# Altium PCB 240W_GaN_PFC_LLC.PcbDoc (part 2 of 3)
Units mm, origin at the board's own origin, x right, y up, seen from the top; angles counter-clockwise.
Board outline 120 x 71.8 mm, 4 copper layers (Top Layer, Layer 1, Layer 2, Bottom Layer), stack 1.787 mm thick; 163 components, 87 nets, 528 pads, 288 vias.
Unrouted connection lines stored in the file: 3.
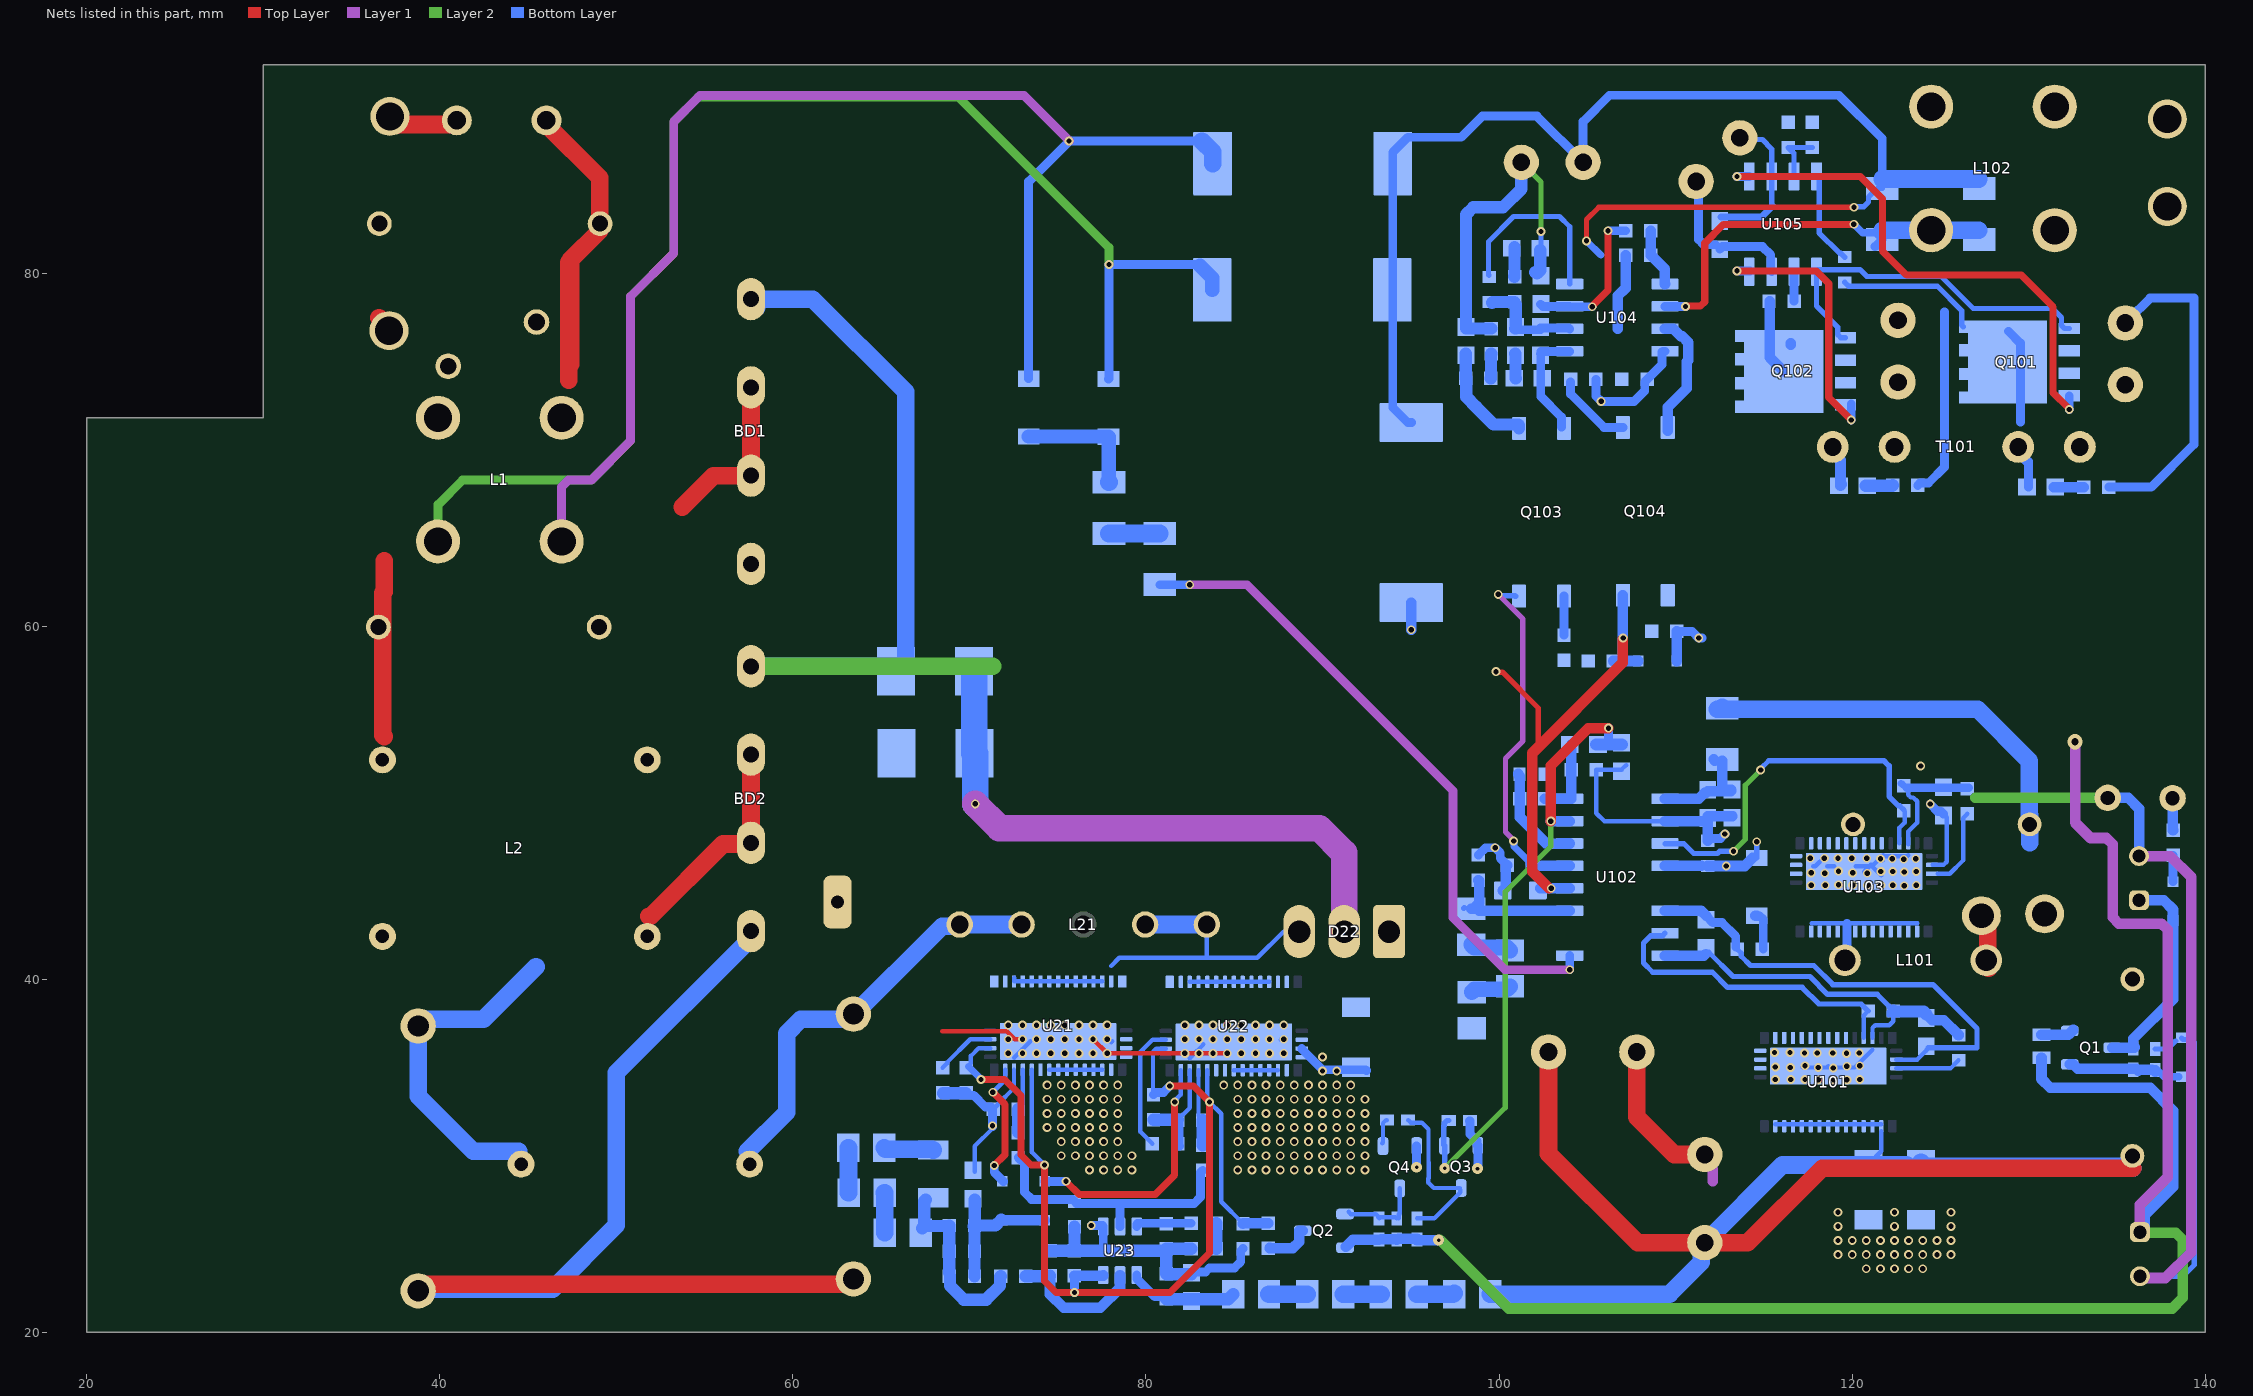
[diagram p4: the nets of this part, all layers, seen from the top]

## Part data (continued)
R121: library part CMP-0023052-4, "RES, 360 k, 1%, 0.1 W, 0603", Manufacturer=Yageo, Power_W=100mW, Supplier Part Number 1=311-360KHRCT-ND, TempCo="100 ppm/C", Tolerance_%=1%, Value2=0.1W, Value_Code=360k
R123: library part CMP-0025821-4, "RES, 4.7, 5%, 0.1 W, AEC-Q200 Grade 0, 0603", Manufacturer=Vishay-Dale, Power_W=100mW, Supplier Part Number 1=541-4.7GCT-ND, TempCo="200 ppm/C", Tolerance_%=5%, Value2=0.1W, Value_Code=4R70, ValueDisplayed=4.7
R124: library part CMP-0023201-5, "RES, 5.49 k, 1%, 0.1 W, 0603", Manufacturer=Yageo, Power_W=100mW, Supplier Part Number 1=311-5.49KHRCT-ND, TempCo="100 ppm/C", Tolerance_%=1%, Value2=0.1W, Value_Code=5k49, ValueDisplayed=5.49k
R125: library part CMP-0022919-4, "RES, 221 k, 1%, 0.1 W, 0603", Manufacturer=Yageo, Power_W=100mW, Supplier Part Number 1=311-221KHRCT-ND, TempCo="100 ppm/C", Tolerance_%=1%, Value2=0.1W, Value_Code=221k
R126: library part CMP-0025768-4, "RES, 2.0 k, 5%, 0.1 W, AEC-Q200 Grade 0, 0603", Manufacturer=Vishay-Dale, Power_W=100mW, Supplier Part Number 1=541-2.0KGCT-ND, TempCo="200 ppm/C", Tolerance_%=5%, Value2=0.1W, Value_Code=2k00, ValueDisplayed=2.0k
R127: library part CMP-0022879-5, "RES, 1.47 k, 1%, 0.1 W, 0603", Manufacturer=Yageo, Power_W=100mW, Supplier Part Number 1=311-1.47KHRCT-ND, TempCo="100 ppm/C", Tolerance_%=1%, Value2=0.1W, Value_Code=1k47, ValueDisplayed=1.47k
R128 R129: library part CMP-0025712-4, "RES, 12, 5%, 0.1 W, AEC-Q200 Grade 0, 0603", Manufacturer=Vishay-Dale, Power_W=100mW, Supplier Part Number 1=541-12GCT-ND, TempCo="200 ppm/C", Tolerance_%=5%, Value2=0.1W, Value_Code=12R0, ValueDisplayed=12
R130 R131: library part CMP-0025912-5, "RES, 330, 5%, 0.1 W, 0603", Manufacturer=Yageo, Power_W=100mW, Supplier Part Number 1=311-330GRCT-ND, TempCo="100 ppm/C", Tolerance_%=5%, Value2=0.1W, Value_Code=330R, ValueDisplayed=330
R132: library part CMP-0022822-4, "RES, 162 k, 1%, 0.1 W, 0603", Manufacturer=Yageo, Power_W=100mW, Supplier Part Number 1=311-162KHRCT-ND, TempCo="100 ppm/C", Tolerance_%=1%, Value2=0.1W, Value_Code=162k
RV1: library part CMP-0001908-4, "VARISTOR 450V 1.2KA DISC 7MM", Manufacturer=Littelfuse
T101: library part XFRM_LLC
TP1 TP2 TP101 TP102 TP103 TP104 TP105 TP106: library part CMP-0055148-1, "Test Point, Multipurpose, Black, TH", Color=Black, Manufacturer=Keystone, PartNumber=5011, Supplier Part Number 1=36-5011-ND
U21 U22: library part CMP-0096535-2, "650-V GaN FET With Integrated Driver and Current Sense Emulation", Manufacturer="Texas Instruments", Max Supply Voltage=26V, Min Supply Voltage=10V, Operating Temperature Range="-40°C to +175°C"
U23: library part CMP-0860501-1, "6-Pin Single-Phase Transition-Mode PFC Controller, DBV0006A (SOT-23-6)", Alternate Manufacturer="Texas Instruments", Operating Temperature Range="-40 to 125 C", Rating=Catalog
U101 U103: library part CMP-0121224-1, "Power Switch/Driver 1:1 N-Channel 7.7A 38-VQFN (8x5.3)", Digikey Part Number=296-LMG3612REQRCT-ND, Manufacturer="Texas Instruments", Max Supply Voltage=26V, Min Supply Voltage=10V, Mouser Part Number=595-LMG3612REQR, Nominal Supply Current=2.2mA, Operating Temperature Range="-40°C to +125°C", Part Number=LMG3612REQR
U102: library part CMP-0095300-2, "750kHz Wide VIN/VOUT Range LLC Controller Optimized for Light Load Efficiency", Manufacturer="Texas Instruments", Max Supply Voltage=18.5V, Operating Temperature Range="-40°C to +150°C", Switching Frequency=30-750kHz
U104: library part CMP-0121574-1, "Dual, 36-V 1.2-MHz low-offset-voltage operational amplifier with internal reference 8-SOIC -40 to 125", Digikey Part Number=296-TL103WBIDRCT-ND, Input Bias Current=-0.015uA, Input Offset Voltage=0.3mV, Manufacturer="Texas Instruments", Max Supply Voltage=36V, Min Supply Voltage=3V, Mouser Part Number=595-TL103WBIDR, Nominal Supply Current=0.55mA, Operating Temperature Range="-40°C to +125°C", Output Current Per Channel=24mA, Voltage Gain=210V/mV
U105: library part CMP-0121571-1, "Power Supply Controller Flyback, Forward Converters, LLC 8-SOIC", Digikey Part Number=1589-MP6924AGS-PTR-ND, Manufacturer="Monolithic Power Systems", Max Power Dissipation=1.4W, Max Supply Voltage=35V, Min Supply Voltage=4.2V, Mouser Part Number=946-MP6924AGS-P, Nominal Supply Current=4.6-16mA, Operating Temperature Range="-40°C to +125°C"

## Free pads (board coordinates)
  rrect50% 1.6x3 hole 0.762 slot 2 at 90 deg: 13(62.525,44.375)

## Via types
v1: diameter 0.5, hole 0.3, Top Layer to Bottom Layer, tented both sides, 283 vias
v2: diameter 0.61, hole 0.203, Top Layer to Bottom Layer, tented both sides, 4 vias
v3: diameter 0.864, hole 0.406, Top Layer to Bottom Layer, tented both sides, 1 vias

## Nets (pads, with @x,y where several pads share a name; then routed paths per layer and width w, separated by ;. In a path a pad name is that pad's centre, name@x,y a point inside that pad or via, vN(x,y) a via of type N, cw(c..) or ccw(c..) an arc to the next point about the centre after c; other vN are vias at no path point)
5VP: C114.1 R119.2 R120.2 U102.8 | length 4.5
  Bottom Layer w0.6: R120.2@102.597,50.229 U102.8@104,50.229 104.089,50.229 C114.1@104.089,51.874 R119.2@104.089,53.272
390V_BUS: C29.1 C30.1 C31.1 C103.1 C122.1 C123.1 D21.1 D22.2 D25.1 R21.2 R109.1 U101.2 U101.3 U101.4 U101.5 U101.6 U101.7 U101.8 U101.9 U101.10 U101.11 U101.12 U101.13 U101.14 | length 125.2
  Top Layer w1: C29.1@102.8,35.875 102.8,30.124 107.849,25.075 C30.1@111.65,25.075 114.071,25.075 118.296,29.3 135.875,29.3
  Layer 1 w1.5: v1(70.325,49.935) 71.696,48.564 89.814,48.564 91.225,47.153 D22.2@91.225,42.7
  Bottom Layer w0.25: U101.14@115.65,31.775 U101.9@118.15,31.775 ; U101.8@118.65,31.775 U101.9@118.15,31.775 ; U101.5@120.15,31.775 U101.4@120.65,31.775 ; C122.1@120.925,29.625 121.025,29.625 121.65,30.25 U101.2@121.65,31.4 ; U101.2@121.65,31.775 U101.4@120.65,31.775 ; U101.9@118.15,31.775 U101.4@120.65,31.775
  Bottom Layer w1: R21.2@99.491,22.15 109.649,22.15 111.459,23.96 111.459,24.884 C30.1@111.65,25.075 116.05,29.475 119.85,29.475 119.862,29.488 122.837,29.488 122.85,29.5 123.075,29.5 ; C29.1@103.15,35.925 C29.1@103.2,35.875 ; C123.1@123.9,29.625 124.125,29.4 135.775,29.4 135.875,29.3
  Bottom Layer w1.5: D25.1@70.26,57.45 70.273,57.437 70.273,52.812 D21.1@70.285,52.8 70.325,52.76 v1(70.325,49.935)
BD+: BD1.1 BD2.1 C25.1 D21.2 D25.2 L22.1 | length 68.9
  Layer 2 w1: BD2.1@57.625,57.725 71.315,57.725
  Bottom Layer w1: L22.1@44.475,30.25 41.9,30.25 38.775,33.375 38.775,37.725 42.475,37.725 45.45,40.7 ; BD2.1@57.625,57.725 66.382,57.725 66.382,73.268 61.123,78.527 57.948,78.527 57.948,78.05 57.625,78.373 BD1.1@57.625,78.527
FB: C116.1 Q103.6 U102.5 | length 20.1
  Layer 1 w0.3: v1(99.95,61.8) 101.347,60.403 101.347,53.496 100.358,52.507 100.358,48.346 100.825,47.879 v1(100.825,47.825) v1@100.871,47.825
  Bottom Layer w0.3: v1(99.95,61.8) 100.004,61.8 100.079,61.725 100.888,61.725 100.913,61.7 Q103.6@100.95,61.7
  Bottom Layer w0.4: v1(100.825,47.825) 100.844,47.806 100.844,47.509 C116.1@101.805,46.548
  Bottom Layer w0.6: C116.1@101.805,46.548 C116.1@101.886,46.467 ; C116.1@101.955,46.419 U102.5@104,46.419
HB: C101.1 C121.2 R106.2 U101.36 U102.14 | length 26.7
  Bottom Layer w0.25: U101.36@122.5,35.45 123.691,35.45 C101.1@124.2,35.959 ; C101.1@124.2,35.984 C101.1@124.316,36.1
  Bottom Layer w0.3: R106.2@113.489,41.7 113.72,41.469 113.72,41.299 114.245,40.774 117.824,40.774 118.905,39.693 124.583,39.693 127.065,37.21 127.065,36.125 127.075,36.125 ; C101.1@124.301,36.125 127.05,36.125
  Bottom Layer w0.5: C121.2@111.725,43.591 112.11,43.206 112.63,43.206 113.408,42.428 R106.2@113.408,41.831
  Bottom Layer w0.6: U102.14@109.4,43.879 111.437,43.879 C121.2@111.725,43.591
HO: C102.1 U101.31 U102.15 | length 18.1
  Bottom Layer w0.25: U101.31@120.65,36.675 120.65,37.947 C102.1@120.903,38.2
  Bottom Layer w0.3: U102.15@109.4,42.609 109.25,42.459 108.58,42.459 108.175,42.054 108.175,40.926 108.707,40.394 110.375,40.394 112.085,40.394 112.94,39.539 117.166,39.539 118.112,38.593 120.51,38.593 C102.1@120.903,38.2
HV: R2.1 U102.1 | length 37.3
  Layer 1 w0.5: v1(82.475,62.348) 85.722,62.348 97.392,50.678 97.392,43.48 100.334,40.537 v1(104,40.537)
  Bottom Layer w0.5: R2.1@80.775,62.35 80.777,62.348 v1(82.475,62.348) ; v1(104,40.537) U102.1@104,41.339
ISNS: C108.2 C120.1 R113.2 U102.9 | length 6.2
  Bottom Layer w0.6: U102.9@109.4,50.229 111.314,50.229 111.652,50.566 111.744,50.566 111.825,50.647 113.119,50.647 113.14,50.669 113.14,50.721 112.65,50.721 C108.2@112.65,52.375 ; C108.2@112.15,52.45 C108.2@112.225,52.375
LL: R120.1 R132.2 U102.6 | length 6
  Bottom Layer w0.6: R132.2@101.075,51.65 101.075,51.598 101.175,51.498 R120.1@101.175,50.229 ; R120.1@101.182,50.229 101.182,49.186 102.688,47.68 103.371,47.68 103.379,47.689 U102.6@104,47.689
LMG_VCC: C21.2 C23.2 C36.1 C39.1 R32.1 U21.30 U21.36 U22.30 U22.36 U23.3 | length 65.8
  Top Layer w0.4: v1(70.65,34.325) 71.994,34.325 72.911,33.408 72.911,30.053 73.489,29.475 v1(74.255,29.475) 74.255,22.905 74.91,22.25 v1(75.95,22.25) 81.35,22.25 ; 77.868,22.25 81.35,22.25 ; v1(81.35,33.95) 82.7,33.95 v1(83.6,33.05) 83.6,24.5 81.35,22.25
  Bottom Layer w0.25: C21.2@69.975,35.136 70.081,35.242 70.081,35.656 70.525,36.1 U21.36@71.175,36.1 ; U21.30@73.525,34.875 73.525,30.211 v1@74.265,29.471 ; C23.2@80.425,33.461 80.397,33.489 80.397,35.891 80.579,36.073 U22.36@81.125,36.073 ; v1@83.475,33.155 U22.30@83.475,34.848 ; v1@83.6,33.028 84.255,32.373 84.255,27.401 C36.1@85.495,26.161
  Bottom Layer w0.254: v1@81.283,33.95 v1(81.35,33.95)
  Bottom Layer w0.4: C21.2@69.946,35.056 70.65,34.352 v1(70.65,34.325)
  Bottom Layer w0.5: v1(75.95,22.25) C39.1@75.95,23.2 ; C23.2@80.425,33.461 80.556,33.592 80.992,33.592 v1(81.35,33.95)
  Bottom Layer w0.6: C39.1@75.95,23.2 C39.1@75.948,23.202 77.577,23.202 U23.3@77.577,23.243 ; C36.1@85.495,26.161 85.502,26.168 86.928,26.168 R32.1@86.935,26.175
LO: C111.1 U102.11 U103.31 | length 21.7
  Layer 2 w0.3: v1(113.275,47.25) 113.943,47.918 113.943,50.983 114.8,51.84 v1@114.8,51.875
  Bottom Layer w0.25: U103.31@122.675,47.7 122.675,48.575 122.975,48.875 122.975,49.525 C111.1@122.95,49.55
  Bottom Layer w0.3: U102.11@109.416,47.674 110.476,47.674 111.025,47.125 112.371,47.125 112.495,47.25 v1(113.275,47.25) ; v1@114.85,51.955 115.274,52.379 121.801,52.379 ; 121.84,52.34 122.095,52.085 122.095,50.357 122.632,49.82 122.694,49.82 C111.1@122.925,49.589
  other v1: 114.816,51.856
NetBD1_2: BD1.2 BD1.3 L2.3 | length 9.6
  Top Layer w1: 53.725,66.75 55.502,68.527 BD1.3@57.625,68.527 BD1.2@57.625,73.527
NetBD2_2: BD2.2 BD2.3 L2.4 | length 12.5
  Top Layer w1: 51.85,43.575 51.952,43.575 56.037,47.66 57.56,47.66 BD2.3@57.625,47.725 BD2.2@57.625,52.725
NetC1_1: C1.1 L1.1 RV1.2 TP1.1 | length 1.1
  Top Layer w1: TP1.1@36.55,77.477 37.125,76.902 TP1.1@37.125,76.575
NetC1_2: C1.2 F1.1 L1.2 RV1.1 | length 28
  Top Layer w1: F1.1@46.015,88.425 49.05,85.39 49.05,82.95 49.05,82.4 47.4,80.75 47.4,74.837 ; 47.3,73.925 47.3,74.837 ; 47.3,74.837 47.3,80.6 47.3,74.837
NetC2_1: C2.1 CY1.1 D3.2 L1.4 L2.2 | length 88.6
  Top Layer w1: C2.1@36.775,59.95 36.775,61.875 ; 36.85,53.75 36.775,53.825 36.775,61.875 ; 36.852,63.702 36.852,61.952 36.775,61.875
  Layer 2 w0.5: L1.4@39.9,64.8 39.9,66.887 41.283,68.27 48.57,68.27 50.8,70.5 50.8,78.675 53.25,81.125 53.25,88.575 54.65,89.975 69.368,89.975 77.903,81.44 77.903,80.488 v1(77.9,80.484)
  Bottom Layer w0.5: D3.2@77.875,74 77.9,74.025 v1(77.9,80.484) 82.979,80.484 CY1.1@83.05,80.413
  Bottom Layer w0.8: CY1.1@83.05,80.413 83.75,79.713 CY1.1@83.75,79.05
NetC2_2: C2.2 CY2.1 D2.2 L1.3 L2.1 | length 74.7
  Layer 1 w0.5: L1.3@46.9,64.8 46.9,67.9 47.275,68.275 48.575,68.275 50.8,70.5 50.8,78.675 53.25,81.125 53.25,88.575 54.725,90.05 73.096,90.05 v1@75.671,87.475
  Bottom Layer w0.5: D2.2@73.35,74.013 73.35,85.182 v1(75.643,87.475) CY2.1@83.175,87.475
  Bottom Layer w1: CY2.1@83.175,87.475 83.775,86.875 CY2.1@83.775,86.2
NetC3_2: C3.2 Q2.1 Q4.3 R6.1 | length 4.7
  Bottom Layer w0.254: Q2.1@91.475,26.825 91.6,26.7 93.027,26.7 93.2,26.527 C3.2@93.2,26.525 ; C3.2@93.15,26.525 C3.2@93.2,26.525 ; C3.2@93.2,26.45 C3.2@93.2,26.525 ; R6.1@94.2,26.45 94.125,26.525 C3.2@93.2,26.525 ; R6.1@94.325,26.45 94.325,26.675 94.375,26.725 Q4.3@94.375,28.15
NetC9_1: C9.1 D4.1 Q1.1 R4.1 | length 6.4
  Bottom Layer w0.4: C9.1@137.2,34.95 137.675,34.475 D4.1@138.5,34.475
  Bottom Layer w0.6: Q1.1@132.325,35.175 132.525,35.175 132.775,34.925 135.925,34.925 136.1,34.925 R4.1@136.2,34.825 ; R4.1@136.2,34.875 C9.1@136.975,34.875 ; C9.1@137.175,34.75 C9.1@137.175,34.85
NetC22_1: C22.1 R34.2 U21.31 | length 3.3
  Bottom Layer w0.25: C22.1@73.025,32.89 U21.31@73.025,34.875
  Bottom Layer w0.7: R34.2@72.77,31.317 C22.1@72.77,32.635
NetC24_1: C24.1 R38.1 U22.31 | length 4.3
  Bottom Layer w0.25: U22.31@82.975,34.848 82.975,32.261 C24.1@83.211,32.025
  Bottom Layer w0.7: R38.1@83.211,30.606 C24.1@83.211,32.025
NetC27_1: C27.1 L21.1 L21.2 L22.2 | length 23.5
  Bottom Layer w1: L22.2@57.425,30.25 59.65,32.475 59.65,36.925 60.45,37.725 63.175,37.725 68.454,43.004 69.354,43.004 L21.1@69.45,43.1 L21.2@72.95,43.1
NetC28_1: C28.1 D22.1 D22.3 L21.4 L21.5 R22.2 U21.1 U21.2 U21.3 U21.4 U21.5 U21.6 U21.7 U21.8 U21.9 U21.10 U21.11 U21.12 U21.13 U21.14 U21.15 U22.1 U22.2 U22.3 U22.4 U22.5 U22.6 U22.7 U22.8 U22.9 U22.10 U22.11 U22.12 U22.13 U22.14 | length 29.3
  Bottom Layer w0.254: U21.3@72.525,40.096 U21.3@72.525,39.875 U21.4@73.025,39.875 U21.5@73.525,39.875 U21.6@74.025,39.875 U21.7@74.525,39.875 U21.8@75.025,39.875 U21.9@75.525,39.875 U21.10@76.025,39.875 U21.11@76.525,39.875 U21.12@77.025,39.875 U21.13@77.525,39.875 ; 78.025,40.75 78.484,41.209 83.436,41.209 ; U22.3@82.475,39.848 U22.4@82.975,39.848 U22.5@83.475,39.848 U22.6@83.975,39.848 U22.7@84.475,39.848 U22.8@84.975,39.848 U22.9@85.475,39.848 U22.10@85.975,39.848 U22.11@86.475,39.848 U22.12@86.975,39.848 ; L21.5@83.45,43.1 83.45,41.224 83.436,41.209 ; D22.3@87.789,42.694 86.304,41.209 83.436,41.209
  Bottom Layer w1: R22.2@65.166,30.45 65.241,30.375 67.9,30.375 C28.1@67.95,30.325 ; L21.4@79.95,43.1 L21.5@83.45,43.1 ; D22.3@88.685,41.884 D22.3@88.685,42.7
NetC28_2: C28.2 C32.1 C33.1 R27.1 R29.2 R33.2 | length 10.4
  Bottom Layer w0.7: R27.1@67.325,25.9 R27.1@67.433,26.008 ; C28.2@67.525,27.5 67.508,27.5 67.433,27.425 R27.1@67.433,26.008 ; C32.1@68.864,23.375 R29.2@68.864,24.6 C33.1@68.864,26.05 68.833,26.019 67.444,26.019 R27.1@67.433,26.008 ; C32.1@68.895,23.206 68.895,22.635 69.68,21.85 70.948,21.85 71.733,22.635 71.733,23.144 R33.2@71.764,23.175
NetC37_1: C37.1 C38.1 U23.6 | length 3.2
  Bottom Layer w0.5: U23.6@79.477,25.993 79.477,26.125 79.527,26.175 C37.1@82.564,26.175
NetC37_2: C37.2 R35.2 | length 1.4
  Bottom Layer w0.7: R35.2@83.986,24.725 C37.2@83.986,26.175
NetC40_1: C40.1 R33.1 U23.2 | length 7.9
  Bottom Layer w0.6: C40.1@74.564,23.195 74.564,22.164 75.336,21.393 77.409,21.393 78.527,22.51 U23.2@78.527,23.243
  Bottom Layer w0.7: R33.1@73.186,23.175 73.196,23.185 74.554,23.185 C40.1@74.564,23.195
NetC41_1: C41.1 R30.1 R37.2 U23.1 | length 6.3
  Bottom Layer w0.5: U23.1@79.477,23.243 79.477,23.043 80.504,22.017 C41.1@81.022,22.017 ; C41.1@81.019,22.02 C41.1@81.022,22.017 ; C41.1@81.094,22.017 C41.1@81.022,22.017 ; C41.1@81.15,21.889 C41.1@81.022,22.017
  Bottom Layer w0.7: C41.1@81.15,21.889 81.162,21.876 82.562,21.876 82.575,21.864 84.649,21.864 R30.1@84.934,22.15
NetC103_2: C103.2 C108.1 C109.1 TP103.1 | length 23.7
  Bottom Layer w1: C108.1@112.362,55.283 C108.1@112.762,55.283 ; C108.1@112.65,55.395 C108.1@112.762,55.283 ; C109.1@130.032,49.232 130.032,52.359 127.108,55.283 C108.1@112.762,55.283 ; 130.05,47.725 C109.1@130.05,49.3
NetC113_2: C113.2 R116.2 | length 1.4
  Bottom Layer w0.7: R116.2@99.536,74.045 99.543,74.052 99.543,75.427 C113.2@99.55,75.434
NetC118_1: C118.1 R103.1 R104.2 R118.2 U104.2 | length 5.8
  Bottom Layer w0.5: R118.2@100.925,76.856 100.991,76.79 C118.1@102.35,76.79 ; C118.1@102.35,76.89 103.95,76.89 U104.2@104,76.84
  Bottom Layer w0.7: R104.2@99.6,78.325 99.639,78.364 R103.1@100.875,78.364 ; R118.2@100.925,76.856 100.938,76.869 R103.1@100.938,78.221
NetC118_2: C118.2 C119.2 Q103.3 U104.1 | length 6.3
  Bottom Layer w0.5: C118.2@102.368,75.452 102.35,75.434 102.356,75.428 102.356,74.051 102.361,74.045 102.361,73.014 103.528,71.847 Q103.3@103.528,71.275 ; C118.2@102.368,75.552 103.982,75.552 U104.1@104,75.57
NetC119_1: C119.1 R118.1 | length 1.4
  Bottom Layer w0.7: R118.1@100.925,75.434 100.932,75.427 100.932,74.052 C119.1@100.939,74.045
NetC125_1: C125.1 R128.1 | length 1.7
  Bottom Layer w0.6: C125.1@131.411,67.875 R128.1@133.114,67.875
NetC126_1: C126.1 R129.1 | length 1.5
  Bottom Layer w0.7: C126.1@120.761,67.95 120.774,67.963 122.276,67.963 R129.1@122.289,67.975
NetC127_2: C127.2 R107.2 U105.3 | length 3.2
  Bottom Layer w0.3: U105.3@116.71,85.475 116.71,86.779 C127.2@116.375,87.114 R107.2@117.75,87.114
NetD1_2: D1.2 Q1.2 | length 1.9
  Bottom Layer w0.6: D1.2@130.725,36.85 132.25,36.85 Q1.2@132.525,37.125
NetD2_1: D2.1 D3.1 R1.2 | length 7.1
  Bottom Layer w0.8: D2.1@73.362,70.737 77.863,70.737 D3.1@77.875,70.725 ; R1.2@77.888,68.162 D3.1@77.888,70.712
  Bottom Layer w1: R1.2@77.888,68.162 R1.2@77.9,68.15
NetD23_2: D23.2 U21.33 | length 7.4
  Top Layer w0.4: v1(71.325,33.6) 72.009,32.916 72.009,30.059 v1(71.4,29.45)
  Bottom Layer w0.25: v1@71.325,33.606 72.025,34.306 U21.33@72.025,34.875
  Bottom Layer w0.5: v1(71.4,29.45) 71.4,29.075 D23.2@71.925,28.55
NetD24_2: D24.2 U22.33 | length 14.2
  Top Layer w0.4: v1(75.473,28.553) 76.218,27.808 80.522,27.808 81.625,28.91 v1(81.625,33.05)
  Bottom Layer w0.25: v1(81.625,33.05) 81.625,33.118 81.975,33.468 U22.33@81.975,34.848
  Bottom Layer w0.5: D24.2@74.275,28.55 75.471,28.55 v1(75.473,28.553)
NetD101_2: D101.2 R123.1 | length 1.5
  Bottom Layer w0.5: D101.2@138.175,45.525 R123.1@138.175,47.025
NetD102_1: D102.1 R106.1 | length 2.2
  Bottom Layer w0.5: D102.1@114.6,43.6 114.753,43.6 114.961,43.391 R106.1@114.961,41.7
  Bottom Layer w0.6: D102.1@114.525,43.6 D102.1@114.6,43.6
NetF1_2: F1.2 TP2.1 | length 3.8
  Top Layer w1: TP2.1@37.125,88.4 37.137,88.413 40.922,88.413 F1.2@40.935,88.425
NetL101_4: L101.4 TP102.1 | length 3
  Top Layer w1: TP102.1@127.65,43.55 127.687,43.512 127.687,40.663 L101.4@127.725,40.625
NetL102_1: L102.1 TP106.1
NetL102_2: L102.2 TP101.1
NetQ2_3: Q2.3 R32.2 | length 2.7
  Bottom Layer w0.6: R32.2@87,24.775 87,24.769 87.016,24.753 88.301,24.753 88.675,25.126 88.675,25.75 Q2.3@88.875,25.75
NetQ3_3: Q3.3 R5.1 R7.2 | length 9.5
  Bottom Layer w0.254: R7.2@94.85,32.025 95.006,31.869 95.631,31.869 96.002,31.498 96.002,29.637 96.007,29.632 96.007,28.732 96,28.725 96,28.475 96.3,28.175 Q3.3@97.775,28.175 ; R5.1@95.35,26.45 96.325,26.45 97.8,27.925 Q3.3@97.8,28.075
NetQ4_1: Q4.1 R7.1 | length 1.5
  Bottom Layer w0.254: Q4.1@93.375,30.7 93.425,30.75 93.425,31.852 93.598,32.025 R7.1@93.65,32.025
NetQ101_4: Q101.4 U105.1 | length 30.3
  Top Layer w0.4: v1(113.475,85.475) 120.457,85.475 121.707,84.225 121.707,81.255 123.066,79.896 129.577,79.896 131.388,78.086 131.388,73.215 v1@132.25,72.353 ; v1@132.25,72.352 v1@132.299,72.303
  Bottom Layer w0.5: v1(113.475,85.475) U105.1@114.17,85.475 ; v1(132.3,72.275) Q101.4@132.3,73.05
NetQ103_1: Q103.1 R116.1 R117.1 | length 6.4
  Bottom Layer w0.7: R117.1@98.125,75.434 98.119,75.428 98.119,74.051 R116.1@98.114,74.045 R116.1@98.145,74.014 ; R116.1@98.145,74.114 R116.1@98.145,74.014 ; Q103.1@101.125,71.2 101.125,71.388 101.088,71.425 99.688,71.425 98.703,72.41 98.703,72.42 98.145,72.978 R116.1@98.145,74.014
NetQ103_4: Q103.4 R112.2 | length 2.2
  Bottom Layer w0.5: R112.2@103.678,59.486 Q103.4@103.678,61.7
NetQ104_1: Q104.1 R126.2 | length 4.4
  Bottom Layer w0.5: R126.2@104.05,73.825 104.05,73.15 105.95,71.25 Q104.1@107.013,71.25
NetQ104_3: Q104.3 U104.7 | length 7.1
  Bottom Layer w0.6: U104.7@109.4,76.84 109.875,76.84 110.295,76.42 110.373,76.42 110.725,76.068 110.725,75.072 110.625,74.972 110.625,73.475 109.55,72.4 Q104.3@109.55,71.075
NetR1_1: R1.1 R2.2 | length 2.9
  Bottom Layer w1: R1.1@77.9,65.25 R2.2@80.775,65.25
NetR3_1: R3.1 R103.2 | length 1.7
  Bottom Layer w0.7: R103.2@100.85,79.811 R103.2@100.875,79.786 R3.1@100.875,81.475
NetR21_1: R21.1 R23.2 | length 2.2
  Bottom Layer w0.254: R23.2@95.338,22.222 R23.2@95.341,22.222
  Bottom Layer w1: R23.2@95.341,22.15 97.392,22.15 R21.1@97.464,22.222
NetR22_1: R22.1 R26.2 | length 2.6
  Bottom Layer w1: R22.1@63.134,30.45 63.146,30.437 63.146,27.913 R26.2@63.159,27.9
NetR23_1: R23.1 R28.2 | length 2.1
  Bottom Layer w1: R28.2@91.166,22.15 R23.1@93.309,22.15
NetR24_2: R24.2 U21.37 | length 3.4
  Bottom Layer w0.25: R24.2@68.475,34.986 68.731,35.242 68.731,35.287 70.044,36.6 U21.37@71.175,36.6
NetR25_2: R25.2 U22.37 | length 7.2
  Bottom Layer w0.25: R25.2@80.364,30.675 79.669,31.37 79.669,35.87 80.015,36.216 80.372,36.573 U22.37@81.125,36.573
NetR26_1: R26.1 R27.2 | length 2.3
  Bottom Layer w1: R26.1@65.191,27.9 65.2,27.891 65.2,25.656 R27.2@65.209,25.647
NetR28_1: R28.1 R30.2 | length 2.2
  Bottom Layer w1: R30.2@86.966,22.15 R28.1@89.134,22.15
NetR101_2: R101.2 U101.37 | length 4
  Bottom Layer w0.25: U101.37@122.5,34.95 125.57,34.95 126.025,35.405 R101.2@126.025,35.414 ; R101.2@125.792,35.174 R101.2@126.022,35.404
NetR105_2: R105.2 U103.37 | length 4.5
  Bottom Layer w0.25: U103.37@124.85,45.975 125.525,45.975 126.281,46.731 126.281,49.12 R105.2@126.525,49.364
NetR109_2: R109.2 R114.2 | length 2.3
  Bottom Layer w0.9: R109.2@98.45,39.266 98.615,39.431 100.46,39.431 R114.2@100.625,39.595
NetR110_2: R110.2 R115.1 U102.3 | length 7.1
  Bottom Layer w0.3: R115.1@98,44.025 R115.1@98.025,44.05
  Bottom Layer w0.6: R115.1@98.425,43.991 98.54,43.991 98.875,44.326 98.875,45.564 R110.2@98.825,45.614 ; R115.1@98.873,43.879 U102.3@104,43.879
NetR114_1: R114.1 R115.2 | length 2.3
  Bottom Layer w0.9: R115.2@98.425,41.959 98.591,41.793 100.459,41.793 R114.1@100.625,41.627
NetR123_2: R123.2 TP105.1 | length 1.8
  Bottom Layer w0.6: TP105.1@138.15,50.25 138.162,50.237 138.162,48.46 R123.2@138.175,48.447
NetR124_1: R124.1 R125.2 U104.3 | length 8.6
  Top Layer w0.4: v1@105.229,78.076 105.325,78.172 105.325,78.175 106.175,79.025 v1(106.175,82.4)
  Bottom Layer w0.5: R124.1@102.35,78.234 102.477,78.107 U104.3@103.997,78.107 ; U104.3@104,78.11 104.015,78.095 v1(105.275,78.095) ; v1@106.212,82.4 R125.2@107.164,82.4
NetR125_1: R125.1 R127.2 U104.5 | length 3.4
  Bottom Layer w0.6: R127.2@108.586,81.02 R125.1@108.586,82.4 ; R127.2@108.588,81.02 108.588,81.018 108.667,80.939 108.669,80.939 109.38,80.229 109.38,79.38 U104.5@109.4,79.38
NetR130_2: R130.2 U105.4 | length 5.3
  Bottom Layer w0.3: U105.4@117.98,85.475 118.131,85.324 118.131,82.279 119.281,81.13 119.345,81.13 R130.2@119.575,80.9
NetR131_2: R131.2 U105.6 | length 1.7
  Bottom Layer w0.5: R131.2@116.711,78.4 U105.6@116.711,80.074
OCP: L102.4 R102.2 R122.2 U104.6 | length 22.5
  Top Layer w0.4: v1@110.625,78.125 110.632,78.132 111.416,78.132 111.65,78.366 111.65,81.692 112.721,82.762 v1(120.096,82.762)
  Bottom Layer w0.4: v1(120.096,82.762) 120.576,82.282 121.318,82.282 R102.2@121.7,81.9
  Bottom Layer w0.5: U104.6@109.4,78.11 109.403,78.107 v1(110.565,78.107) ; R102.2@121.3,81.5 R102.2@121.7,81.9
  Bottom Layer w1: R102.2@121.703,82.425 R122.2@127.175,82.425
OTP: D103.2 Q104.6 R108.2 R111.2 U102.4 | length 28.6
  Top Layer w0.3: v1(99.825,57.425) 99.857,57.393 100.182,57.393 102.225,55.35 102.225,53.4 102.349,53.276 102.35,53.275
  Top Layer w0.6: v1@102.825,45.149 101.89,46.084 101.89,52.817 107.011,57.938 v1@107.011,59.247
  Bottom Layer w0.6: R108.2@102.324,45.149 U102.4@104,45.149 ; R111.2@106.461,58.025 D103.2@107.875,58.025 ; 107.013,58.194 v1@107.013,59.247 ; v1@107.013,59.325 Q104.6@107.013,61.75
  other v1: 102.95,45.15 107.025,59.325
PFC_CS: C32.2 C33.2 D23.1 D24.1 R29.1 R31.2 | length 8.4
  Bottom Layer w0.6: D23.1@71.85,26.35 D24.1@74.275,26.35
  Bottom Layer w0.7: C33.2@70.225,26 70.3,26.075 R31.2@70.3,27.5 ; C32.2@70.286,23.175 R29.1@70.286,24.6 C33.2@70.286,26 ; C33.2@70.286,26.05 71.475,26.05 D23.1@71.8,26.375
PFC_G: R34.1 R36.2 R38.2 U23.5 | length 15.4
  Bottom Layer w0.5: R34.1@72.77,29.895 73.117,29.548 73.117,27.933 73.522,27.528 75.833,27.528 76.067,27.294 78.527,27.294 ; U23.5@78.527,25.993 78.527,27.294 ; R38.2@83.211,29.183 83.08,29.052 83.08,27.649 82.725,27.294 78.527,27.294
PGND: BD1.4 BD2.4 C4.2 C5.2 C9.2 C21.1 C22.2 C23.1 C24.2 C25.2 C27.2 C29.2 C30.2 C31.2 C36.2 C38.2 C39.2 C40.2 C41.2 C109.2 C110.2 C111.2 C112.2 C114.2 C116.2 C117.1 C120.2 C122.2 C123.2 C128.1 CY101.2 D4.2 pad.13 Q3.2 Q4.2 Q104.4 R24.1 R25.1 R31.1 R35.1 R36.1 R37.1 R105.1 R108.1 R110.1 R111.1 R112.1 R113.1 R121.1 R132.1 TP104.1 U21.17 U21.18 U21.19 U21.21 U21.22 U21.23 U21.24 U21.25 U21.26 U21.27 U21.28 U21.29 U21.32 U21.39 U22.17 U22.18 U22.19 U22.21 U22.22 U22.23 U22.24 U22.25 U22.26 U22.27 U22.28 U22.29 U22.32 U22.39 U23.4 U102.10 U103.17 U103.18 U103.19 U103.21 U103.22 U103.23 U103.24 U103.25 U103.26 U103.27 U103.28 U103.29 U103.32 U103.39 | length 223.4
  Top Layer w0.254: 68.463,37.045 72.119,37.045 72.564,36.6 v1(73,36.6) ; v1(77,36.6) v1(77.8,35.8) v1(82.2,35.8) v1(83,35.8) v1(83.8,35.8) v1(84.6,35.8)
  Top Layer w1: C25.2@38.775,22.725 C27.2@63.175,22.725 ; C29.2@107.8,35.875 107.8,32.194 109.919,30.075 C30.2@111.65,30.075
  Layer 1 w0.6: C30.2@111.65,30.075 111.65,29.696 112.108,29.238 112.108,28.552 ; C112.2@136.249,46.973 138.019,46.973 139.2,45.792 139.2,24.532 137.743,23.075 136.543,23.075 136.471,23.146 C4.2@136.471,23.204
  Layer 2 w0.6: 126.975,50.275 TP104.1@134.475,50.275
  Bottom Layer w0.25: R31.1@70.3,29.1 70.3,30.55 71.3,31.55 v1@71.3,31.65 ; 72.523,33.846 72.525,33.848 U21.32@72.525,34.875 ; C24.2@81.803,32.039 82.475,32.711 U22.32@82.475,34.848 ; U22.39@82.475,35.525 U22.39@82.598,35.648 ; R121.1@107.196,52.131 106.94,51.875 C114.2@105.511,51.874 ; U102.10@109.4,48.95 105.969,48.95 105.511,49.408 C114.2@105.511,51.874 ; U103.39@117.8,46.4 117.915,46.4 U103.39@118.465,46.95 ; U103.39@118.6,46.4 U103.39@118.995,46.4 ; U103.39@120.2,46.4 121.125,46.4 U103.39@121.65,45.875 ; U103.39@120.675,46.1 121.05,46.475 121.199,46.475 U103.39@121.749,47.025 ; U103.39@121.725,46.725 121.725,46.863 121.749,46.887 U103.39@121.749,47.025 ; C111.2@123.087,50.85 123.181,50.756 123.181,50.441 123.327,50.295 123.461,50.295 123.681,50.075 123.681,48.874 123.175,48.368 ; U103.39@123.175,47.025 123.125,46.975 121.799,46.975 U103.39@121.749,47.025 ; U103.32@123.175,47.65 123.175,48.325 ; C114.2@105.511,51.874 C114.2@105.511,51.874
  Bottom Layer w0.254: C22.2@71.348,32.635 71.602,32.889 71.602,32.923 72.523,33.844 72.523,33.846 ; U21.39@72.537,35.564 U21.39@73,36.027 ; v1(73,35.8) U21.39@73,36.027 ; U21.39@73.448,36.475 U21.39@73,36.027 ; U21.28@74.525,34.875 U21.27@75.025,34.875 U21.26@75.525,34.875 U21.25@76.025,34.875 U21.24@76.525,34.875 U21.23@77.025,34.875 U21.22@77.525,34.875 ; U21.39@78.025,36.425 U21.39@78.075,36.475 ; U22.39@82.598,35.648 U22.39@83.256,36.307 ; U22.27@84.975,34.848 U22.26@85.475,34.848 U22.25@85.975,34.848 U22.24@86.475,34.848 U22.23@86.975,34.848 U22.22@87.475,34.848 ; U22.39@87.629,36.571 87.658,36.6 v1(87.8,36.6)
  Bottom Layer w0.3: C4.2@136.2,23.1 136.275,23.175 C4.2@136.3,23.175 138.732,23.175 139.375,23.818 139.375,36.412 139.199,36.588 138.737,36.588 D4.2@138.65,36.675 ; C9.2@137.175,36.05 137.875,36.05 138.325,36.5
  Bottom Layer w0.4: C120.2@113.2,49.239 C120.2@113.286,49.325 ; C111.2@122.776,51.099 C111.2@122.875,51
  Bottom Layer w0.5: C21.1@69.832,33.571 69.832,33.556 69.956,33.433 70.237,33.433 70.904,32.766 70.915,32.766 70.925,32.756 71.226,32.756 71.3,32.682 v1@71.3,31.65 ; v1(76.9,26.05) 77.527,26.05 77.577,26 U23.4@77.577,25.993 77.577,24.618 ; R25.1@81.786,30.675 R25.1@81.9,30.561 ; R37.1@82.575,23.286 82.706,23.417 83.367,23.417 83.6,23.65 85.016,23.65 85.364,23.998 85.364,24.608 C36.2@85.495,24.739 ; U22.18@88.825,36.073 88.825,36.048 89.998,34.875 92.45,34.875 C31.2@92.493,34.832 ; R110.1@98.825,47.036 99.239,47.45 v1(99.775,47.45) 100.068,47.157 100.068,46.863 C116.2@100.464,46.467 ; C117.1@111.825,47.836 111.825,47.845 111.956,47.976 112.54,47.976 v1(112.789,48.225) ; C111.2@123.087,50.85 R105.1@126.6,50.85
  Bottom Layer w0.508: v2@95.325,29.325 Q4.2@95.325,30.55 ; C5.2@98.325,31.975 98.339,31.961 98.339,31.236 98.754,30.821 98.754,30.621 Q3.2@98.8,30.575 98.8,29.375 v2@98.75,29.325
  Bottom Layer w0.6: v1(95.025,59.8) 95.025,61.326 CY101.2@95.035,61.336 ; R108.1@100.2,45.025 100.387,45.212 100.387,46.391 C116.2@100.464,46.467 ; U102.10@109.4,48.959 R113.1@111.559,48.959 ; C117.1@111.825,47.845 111.825,49.225 111.832,49.232 113.193,49.232 C120.2@113.2,49.239 ; TP104.1@134.475,50.275 135.631,50.275 136.25,49.656 C112.2@136.25,46.975
  Bottom Layer w0.7: R24.1@68.5,33.538 C21.1@69.8,33.538 ; C40.2@74.556,24.609 C40.2@74.564,24.618 77.577,24.618 81.029,24.618 C38.2@81.15,24.739 ; C39.2@75.948,24.624 R36.1@75.949,25.988 ; C23.1@80.425,32.039 C24.2@81.803,32.039 ; R25.1@81.786,30.675 81.787,30.676 C24.2@81.789,32.025 C24.2@81.789,32.025 ; R35.1@82.564,24.725 82.557,24.732 81.157,24.732 C38.2@81.15,24.739 ; R37.1@82.575,23.286 82.567,23.294 81.167,23.294 C41.2@81.15,23.311 C38.2@81.15,24.739
  Bottom Layer w1: C25.2@38.775,22.35 38.877,22.452 46.388,22.452 50,26.064 50,34.7 57.625,42.325 BD2.4@57.625,42.725 ; pad.13@62.525,43.675 pad.13@62.525,44.375 ; C27.2@63.387,23.113 C27.2@63.45,23.05
  other v1: 120.8,23.6 121.6,23.6 122.4,23.6 123.2,23.6 124,23.6 119.2,24.4 120,24.4 120.8,24.4 121.6,24.4 122.4,24.4 123.2,24.4 124,24.4 124.8,24.4 125.6,24.4 119.2,25.2 120,25.2 120.8,25.2 121.6,25.2 122.4,25.2 123.2,25.2 124,25.2 124.8,25.2 125.6,25.2 119.2,26 122.4,26 125.6,26 119.2,26.8 122.4,26.8 125.6,26.8 76.8,29.2 77.6,29.2 78.4,29.2 79.2,29.2 85.2,29.2 86,29.2 86.8,29.2 87.6,29.2 88.4,29.2 89.2,29.2 90,29.2 90.8,29.2 91.6,29.2 92.4,29.2 75.2,30 76,30 76.8,30 77.6,30 78.4,30 79.2,30 85.2,30 86,30 86.8,30 87.6,30 88.4,30 89.2,30 90,30 90.8,30 91.6,30 92.4,30 75.2,30.8 76,30.8 76.8,30.8 77.6,30.8 78.4,30.8 85.2,30.8 86,30.8 86.8,30.8 87.6,30.8 88.4,30.8 89.2,30.8 90,30.8 90.8,30.8 91.6,30.8 92.4,30.8 74.4,31.6 75.2,31.6 76,31.6 76.8,31.6 77.6,31.6 78.4,31.6 85.2,31.6 86,31.6 86.8,31.6 87.6,31.6 88.4,31.6 89.2,31.6 90,31.6 90.8,31.6 91.6,31.6 92.4,31.6 71.3,31.7 74.4,32.4 75.2,32.4 76,32.4 76.8,32.4 77.6,32.4 78.4,32.4 85.2,32.4 86,32.4 86.8,32.4 87.6,32.4 88.4,32.4 89.2,32.4 90,32.4 90.8,32.4 91.6,32.4 92.4,32.4 74.4,33.2 75.2,33.2 76,33.2 76.8,33.2 77.6,33.2 78.4,33.2 85.2,33.2 86,33.2 86.8,33.2 87.6,33.2 88.4,33.2 89.2,33.2 90,33.2 90.8,33.2 91.6,33.2 92.4,33.2 74.4,34 75.2,34 76,34 76.8,34 77.6,34 78.4,34 84.4,34 85.2,34 86,34 86.8,34 87.6,34 88.4,34 89.2,34 90,34 90.8,34 91.6,34 90,34.8 90.8,34.8 90,35.6 72.2,35.8 73.8,35.8 74.6,35.8 75.4,35.8 76.2,35.8 77,35.8 85.4,35.8 86.2,35.8 87,35.8 87.8,35.8 72.2,36.6 73.8,36.6 74.6,36.6 75.4,36.6 76.2,36.6 77.8,36.6 82.2,36.6 83,36.6 83.8,36.6 84.6,36.6 85.4,36.6 86.2,36.6 87,36.6 72.2,37.4 73,37.4 73.8,37.4 74.6,37.4 75.4,37.4 76.2,37.4 77,37.4 77.8,37.4 82.2,37.4 83,37.4 83.8,37.4 84.6,37.4 85.4,37.4 86.2,37.4 87,37.4 87.8,37.4 122.95,45.3 117.675,45.325 118.475,45.325 120.025,45.325 120.875,45.325 121.625,45.325 122.3,45.325 123.625,45.325 119.225,45.35 118.45,46 120.85,46 117.675,46.025 120.025,46.025 122.95,46.075 121.625,46.1 122.3,46.1 123.625,46.1 119.225,46.125 122.925,46.8 117.625,46.85 118.425,46.85 119.2,46.85 119.975,46.85 120.825,46.85 121.6,46.825 122.275,46.825 123.6,46.825 123.88,52.081
  other v2: 98.775,29.275 95.325,29.35
RTN: C104.2 C105.2 C106.2 C107.2 C115.2 C124.2 C127.1 CY1.2 CY2.2 CY101.1 Q101.1 Q101.2 Q101.3 Q102.1 Q102.2 Q102.3 R102.1 R104.1 R107.1 R122.1 R127.1 R128.2 R129.2 U104.4 U105.2 U105.5 | length 150.6
  Top Layer w0.3: v1(104.95,81.825) 104.95,83.025 105.65,83.725 v1(120.1,83.725)
  Top Layer w0.5: C104.2@104.76,86.275 C104.2@105.01,86.275
  Bottom Layer w0.3: R104.1@99.425,79.875 99.4,79.9 99.4,81.775 100.825,83.2 103.425,83.2 104,82.625 U104.4@104,79.38 ; C105.2@113.637,87.662 113.738,87.561 114.912,87.561 115.44,87.033 U105.2@115.44,85.475 115.44,83.855 115.495,83.8 ; Q102.1@119.625,76.34 119.35,76.34 119.175,76.515 119.175,76.937 117.98,78.132 U105.5@117.98,80.075 118.1,80.195 120.443,80.195 120.829,79.808 125.049,79.808 126.86,77.996 131.337,77.996 131.86,77.474 131.86,77.035 132.035,76.86 Q101.1@132.3,76.86 ; v1(120.1,83.725) 120.138,83.763 120.667,83.763 120.925,84.021 120.925,84.3 121.421,84.796 R102.1@121.7,84.796
  Bottom Layer w0.4: v1(104.95,81.825) 104.956,81.825 105.761,81.02 ; C115.2@112.575,83.175 114.87,83.175 115.495,83.8
  Bottom Layer w0.5: CY101.1@95.035,71.536 94.825,71.536 93.975,72.386 CY2.2@93.975,86.2 93.975,86.845 94.825,87.695 97.858,87.695 99.055,88.891 102.143,88.891 C104.2@104.76,86.275 104.76,88.578 106.257,90.075 119.25,90.075 121.703,87.622 R102.1@121.703,85.325 ; R129.2@123.711,67.975 123.842,68.106 124.325,68.106 125.222,69.003 125.222,77.794 ; R128.2@134.536,67.875 136.938,67.875 139.354,70.292 139.354,78.579 136.879,78.579 135.675,77.375 C106.2@135.675,77.3
  Bottom Layer w0.6: 106.725,76.838 106.725,78.71 107.164,79.148 R127.1@107.164,81.02
  Bottom Layer w1: R102.1@121.703,85.325 R122.1@127.175,85.325
SW: C101.2 C102.2 C121.1 L101.1 R101.1 U101.17 U101.18 U101.19 U101.21 U101.22 U101.23 U101.24 U101.25 U101.26 U101.27 U101.28 U101.29 U101.32 U101.39 U102.16 U103.2 U103.3 U103.4 U103.5 U103.6 U103.7 U103.8 U103.9 U103.10 U103.11 U103.12 U103.13 U103.14 | length 34
  Bottom Layer w0.25: U101.39@117.2,35 120.15,35 U101.39@121.15,36 ; 117.7,43.175 119.7,43.175 123.7,43.175 ; U101.39@118.575,35 U101.39@118.65,35.075 ; U101.32@121.15,36.675 121.15,37.25 121.3,37.4 122.1,37.4 122.325,37.625 C102.2@122.325,37.875 ; C102.2@122.069,37.944 C102.2@122.069,38.158 ; C102.2@122.218,38.307 C102.2@122.242,38.331
  Bottom Layer w0.3: C121.1@111.876,41.531 113.256,40.15 117.604,40.15 118.612,39.143 121.423,39.143 122.094,38.472 122.094,38.431 122.218,38.307 C102.2@122.325,38.2
  Bottom Layer w0.5: C121.1@111.639,41.389 C121.1@111.725,41.475 ; 119.7,43.175 119.708,43.168 119.708,40.632 L101.1@119.715,40.625
  Bottom Layer w0.6: U102.16@109.4,41.339 111.589,41.339 C121.1@111.639,41.389 ; C102.2@122.325,38.2 C102.2@122.341,38.216 ; C101.2@124.2,38.016 124.535,37.681 125.189,37.681 126.025,36.845 R101.1@126.025,36.836
  Bottom Layer w0.7: C102.2@122.341,38.216 122.341,38.184 122.356,38.169 124.047,38.169 C101.2@124.2,38.016
  other v1: 118.075,34.3 118.95,34.3 119.7,34.3 115.65,34.325 116.525,34.325 117.325,34.325 120.425,34.325 118.925,34.975 116.5,35 118.075,35 115.65,35.025 119.7,35.075 117.325,35.1 120.425,35.1 119.675,35.8 117.3,35.825 118.025,35.825 118.9,35.825 120.4,35.825 115.6,35.85 116.475,35.85
TSET: C5.1 Q3.1 R119.1 R121.2 U102.7 | length 35.7
  Top Layer w0.6: v1(102.933,48.954) 102.933,52.098 105.049,54.214 v1@106.189,54.214
  Layer 2 w0.305: v2(96.925,29.3) 100.35,32.725 100.35,44.95 102.933,47.533 v1(102.933,48.954)
  Bottom Layer w0.305: v2@96.875,29.275 96.912,29.312 Q3.1@96.912,30.563 ; Q3.1@96.875,30.625 96.875,31.674 96.902,31.701 96.902,31.852 97.05,32 C5.1@97.15,32
  Bottom Layer w0.5: v1(106.2,54.225) 106.2,53.324 106.226,53.299
  Bottom Layer w0.6: v1(102.933,48.954) 102.937,48.95 U102.7@104,48.95 ; R119.1@105.511,53.3 R119.1@105.513,53.299 ; R121.2@106.939,53.299 R121.2@106.94,53.297
  Bottom Layer w0.7: R119.1@105.513,53.299 106.226,53.299 R121.2@106.939,53.299
VAUX: C112.1 D101.1 Q1.3 R4.2 | length 12.1
  Bottom Layer w0.6: Q1.3@134.725,36.125 135.925,36.125 135.925,36.625 138.175,38.875 D101.1@138.175,43.325 ; R4.2@135.975,36.125 R4.2@136,36.15 ; C112.1@136.25,44.475 137.65,44.475 138.175,43.95 D101.1@138.175,43.4
VCCP: C3.1 C4.1 C110.1 C117.2 C128.2 D1.1 D102.2 D103.1 Q2.2 R5.2 R6.2 U102.12 U103.36 | length 118.5
  Layer 1 w0.6: v3@132.55,53.4 132.553,53.4 132.625,53.328 132.625,48.876 133.501,48 134.399,48 134.75,47.649 134.75,43.501 135.101,43.15 137.524,43.15 137.875,42.799 137.875,28.8 136.3,27.225 C4.1@136.3,25.675 ; C4.1@136.3,25.5 C4.1@136.4,25.6
  Layer 2 w0.6: v2@96.65,25.25 100.55,21.35 138.125,21.35 138.725,21.95 138.725,25.249 138.324,25.65 C4.1@136.05,25.65 ; v3@132.6,53.375 v3@132.625,53.35
  Bottom Layer w0.25: U103.36@124.55,46.475 125.175,46.475 125.357,46.657 125.357,49.182 C110.1@125.175,49.364
  Bottom Layer w0.3: D102.2@114.6,46.875 v1@114.6,47.782
  Bottom Layer w0.5: C128.2@110.061,59.7 110.939,59.7 v1(111.314,59.325) v1@111.5,59.325 ; v1(124.425,49.925) 124.425,49.924 124.854,49.495 125.044,49.495 C110.1@125.175,49.364
  Bottom Layer w0.6: Q2.2@91.325,24.85 91.725,25.25 C3.1@93.2,25.25 ; C3.1@93.325,25.275 94.2,25.275 R6.2@94.2,25.25 ; R6.2@94.325,25.3 95.35,25.3 R5.2@95.35,25.25 ; R5.2@95.35,25.225 v2(96.575,25.225) ; U102.12@109.4,46.419 C117.2@111.455,46.419 ; C128.2@110.061,59.7 110.075,59.686 D103.1@110.075,58.025 ; C117.2@111.825,46.414 v1(112.868,46.414) 113.911,46.414 D102.2@114.373,46.875 ; D1.1@130.725,35.55 130.725,34.35 131.225,33.85 ; 131.4,33.85 136.875,33.85 138.175,32.55 138.175,28.25 136.563,26.638 136.563,25.813 C4.1@136.425,25.675
  other v1: 114.593,47.789
  other v3: 132.625,53.45
VDH: C125.2 Q101.5 Q101.6 Q101.7 Q101.8 Q101.9 R130.1 T101.4 | length 16.1
  Bottom Layer w0.3: R130.1@119.575,79.478 119.795,79.258 124.821,79.258 126.2,77.879 126.2,77.055 Q101.8@126.3,76.955
  Bottom Layer w0.5: Q101.9@128.853,76.705 129.528,76.03 129.528,71.558 ; T101.4@129.4,70.15 129.4,69.798 129.864,69.335 ; C125.2@129.989,67.875 129.989,69.335
VDL: C126.2 Q102.5 Q102.6 Q102.7 Q102.8 Q102.9 R131.1 T101.1 | length 6.9
  Bottom Layer w0.6: R131.1@115.339,78.406 115.339,75.221 Q102.9@116.125,74.435 ; Q102.9@116.525,75.93 Q102.9@116.525,76.03 ; T101.1@118.9,70.15 118.9,69.825 119.339,69.387 119.339,67.95 C126.2@119.42,68.031
VFB: C104.1 C105.1 C106.1 C107.1 C113.1 C115.1 C124.1 L102.3 R3.2 R117.2 R124.2 R126.1 T101.2 T101.5 U104.8 U105.7 | length 35.5
  Top Layer w0.5: L102.3@131.475,82.475 L102.3@131.475,82.886
  Layer 2 w0.3: C104.1@101.41,86.125 102.375,85.16 v1(102.375,82.35)
  Bottom Layer w0.3: R3.2@102.325,81.3 102.375,81.35 v1(102.375,82.35)
  Bottom Layer w0.5: R126.1@105.487,73.975 105.487,73.024 v1(105.78,72.732) 107.656,72.732 108.25,73.326 108.25,73.844 109.219,74.813 109.219,75.52 109.269,75.57 U104.8@109.4,75.57 ; C105.1@111.163,85.188 111.303,85.047 111.303,81.899 111.601,81.6 C115.1@112.275,81.6 ; C115.1@112.5,81.35 112.651,81.501 114.916,81.501 115.385,81.032 115.385,80.13 U105.7@115.44,80.075
  Bottom Layer w0.7: R117.2@98.125,76.856 C113.1@99.55,76.856 ; R117.2@98.125,76.945 98.125,83.315 98.535,83.725 100.225,83.725 101.26,84.76 C104.1@101.26,86.125 ; R124.2@102.05,80.05 R124.2@102.15,80.05 ; R124.2@102.15,79.975 102.325,80.15 R3.2@102.325,81.3
VGL: Q102.4 U105.8 | length 15.4
  Top Layer w0.4: v1@113.481,80.119 117.964,80.119 118.675,79.408 118.675,72.95 v1(119.95,71.675)
  Top Layer w0.5: v1(113.475,80.125) v1@113.481,80.119
  Bottom Layer w0.5: v1(113.475,80.125) U105.8@114.225,80.125 ; v1(119.95,71.675) Q102.4@119.95,72.575
pads on no net: L21.3 L101.2 L101.3 T101.3 U21.16 U21.20 U21.34 U21.35 U21.38 U22.15 U22.16 U22.20 U22.34 U22.35 U22.38 U101.1 U101.15 U101.16 U101.20 U101.30 U101.33 U101.34 U101.35 U101.38 U103.1 U103.15 U103.16 U103.20 U103.30 U103.33 U103.34 U103.35 U103.38
copper on no net: | length 2.1
  Bottom Layer w0.25: v1(121.85,49.225) 121.85,49.157 122.175,48.832 122.175,47.9
  Bottom Layer w0.3: 113.475,36.625 113.483,36.617 114.112,36.617

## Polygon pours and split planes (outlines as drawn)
NetC103_2 on Bottom Layer "BOTTOM_LAYER_NETC103_2_P082" (solid, remove dead copper, pour order 207): 129.375,49.42 129.375,46.35 129.75,45.975 129.75,42.025 133.125,38.65 136,38.65 136.7,39.35 136.7,40.55 136.475,40.775 135.25,40.775 132.1,43.925 132.1,46.675 130.7,48.075 130.7,49.42
390V_BUS on Bottom Layer "BOTTOM_LAYER_390V_BUS_P270" (solid, remove dead copper, pour order 270): 69.215,59.484 69.215,51.475 71.925,51.475 71.925,59.484
BD+ on Bottom Layer "BOTTOM_LAYER_BD+_P264" (solid, remove dead copper, pour order 264): 19 vertices, not listed, extent 52.675,51.475 66.925,90.525
NetBD2_2 on Bottom Layer "BOTTOM_LAYER_NETBD2_2_P261" (solid, remove dead copper, pour order 261): 17 vertices, not listed, extent 50.6,41.375 59,54.075
NetC2_1 on Bottom Layer "BOTTOM_LAYER_NETC2_1_P257" (solid, remove dead copper, pour order 257): 40.975,66.275 37.225,66.275 35.25,64.3 35.275,64.275 35.275,52.5 36.2,51.575 37.25,51.575 38.425,52.75 38.425,58.85 37.8,59.475 37.8,60.175 38.65,61.025 40,61.025 41.55,62.575 41.55,65.7
NetC2_2 on Bottom Layer "BOTTOM_LAYER_NETC2_2_P238" (solid, remove dead copper, pour order 238): 27 vertices, not listed, extent 35.25,41.375 49.962,66.65
NetC2_2 on Bottom Layer "BOTTOM_LAYER_NETC2_2_P258" (solid, remove dead copper, pour order 258): 27 vertices, not listed, extent 35.25,41.375 49.962,66.65
BD+ on Bottom Layer "BOTTOM_LAYER_BD+_P252" (solid, remove dead copper, pour order 252): 64.1,90.525 67.925,90.525 70,88.45 70,63.4 66.55,59.95 63.999,59.95
NetC1_2 on Bottom Layer "BOTTOM_LAYER_NETC1_2_P250" (solid, remove dead copper, pour order 250): 19 vertices, not listed, extent 44.15,70.625 50.125,90.525
NetC1_1 on Bottom Layer "BOTTOM_LAYER_NETC1_1_P246" (solid, remove dead copper, pour order 246): 22 vertices, not listed, extent 35.4,69.9 41.725,83.7
NetF1_2 on Bottom Layer "BOTTOM_LAYER_NETF1_2_P243" (solid, remove dead copper, pour order 243): 41.8,88.125 41.2,87.525 35.65,87.525 35.25,87.925 35.25,89.925 36,90.675 40.725,90.675 41.8,89.6
NetBD1_2 on Bottom Layer "BOTTOM_LAYER_NETBD1_2_P239" (solid, remove dead copper, pour order 239): 58.425,75 51.425,75 50.525,74.1 50.525,68.575 52.075,67.025 58.1,67.025 59.25,68.175 59.25,74.175
PGND on Bottom Layer "BOTTOM_LAYER_PGND_P233" (solid, remove dead copper, pour order 233): 26 vertices, not listed, extent 36.3,21.05 65.325,48.625
NetBD2_2 on Bottom Layer "BOTTOM_LAYER_NETBD2_2_P229" (solid, remove dead copper, pour order 229): 17 vertices, not listed, extent 50.6,41.375 59,54.075
BD+ on Bottom Layer "BOTTOM_LAYER_BD+_P231" (solid, remove dead copper, pour order 231): 27 vertices, not listed, extent 36.825,28.65 55.9,59.325
NetC28_1 on Bottom Layer "BOTTOM_LAYER_NETC28_1_P161" (solid, remove dead copper, pour order 161): 35 vertices, not listed, extent 64.54,29.775 94.65,47.65
RTN on Bottom Layer "BOTTOM_LAYER_RTN_P224" (solid, remove dead copper, pour order 224): 20 vertices, not listed, extent 103.213,73.6 108.3,81.4
PGND on Bottom Layer "BOTTOM_LAYER_PGND_P221" (solid, remove dead copper, pour order 221): 18 vertices, not listed, extent 115.425,45.105 124,51.95
PGND on Bottom Layer "BOTTOM_LAYER_PGND_P210" (solid, remove dead copper, pour order 210): 133.65,49.975 134.3,49.325 135.2,49.325 135.65,48.875 135.65,46.65 135.95,46.35 136.575,46.35 136.825,46.6 136.825,50.925 136.325,51.425 134.075,51.425 133.65,51
NetR123_2 on Bottom Layer "BOTTOM_LAYER_NETR123_2_P209" (solid, remove dead copper, pour order 209): 137.275,48.6 137.8,48.075 139.2,48.075 139.6,48.475 139.6,50.9 139.1,51.4 137.675,51.4 137.275,51
NetL101_4 on Bottom Layer "BOTTOM_LAYER_NETL101_4_P205" (solid, remove dead copper, pour order 205): 126.2,44.55 126.2,40.85 127.175,39.875 128.225,39.875 128.725,40.375 128.725,41.658 128.5,41.883 128.5,44.975 128.15,45.325 126.975,45.325
390V_BUS on Bottom Layer "BOTTOM_LAYER_390V_BUS_P186" (solid, remove dead copper, pour order 186): 40 vertices, not listed, extent 90.4,21.025 136.96,42.641
NetC27_1 on Bottom Layer "BOTTOM_LAYER_NETC27_1_P197" (solid, remove dead copper, pour order 197): 20 vertices, not listed, extent 55.55,27.891 73.74,46
PGND on Bottom Layer "BOTTOM_LAYER_PGND_P196" (solid, remove dead copper, pour order 196): 20 vertices, not listed, extent 81.675,25.175 93.25,37.75
PGND on Bottom Layer "BOTTOM_LAYER_PGND_P195" (solid, remove dead copper, pour order 195): 18 vertices, not listed, extent 71.725,27.775 81.3,37.8
VFB on Bottom Layer "BOTTOM_LAYER_VFB_P160" (solid, remove dead copper, pour order 160): 134.718,74.65 138.282,74.65 138.785,74.147 138.785,70.618 136.989,68.822 132.46,68.822 131.733,69.548 131.733,71.27 131.935,71.472 132.76,71.472 133.435,72.147 133.435,73.366
VFB on Bottom Layer "BOTTOM_LAYER_VFB_P190" (solid, remove dead copper, pour order 190): 121.59,73.765 120.765,72.94 120.765,69.683 121.44,69.008 124.29,69.008 124.715,69.433 124.715,74.533 124.415,74.833 122.14,74.833 121.59,74.283
OCP on Bottom Layer "BOTTOM_LAYER_OCP_P189" (solid, remove dead copper, pour order 189): 121.425,83.8 127.725,83.8 128.125,83.4 128.125,80.826 127.553,80.254 121.447,80.254 120.775,80.926 120.775,83.15
RTN on Bottom Layer "BOTTOM_LAYER_RTN_P188" (solid, remove dead copper, pour order 188): 92.725,70.975 93.253,70.447 97.747,70.447 98.5,71.2 98.5,81.344 99.595,82.439 99.595,87.024 100.32,87.75 102.106,87.75 103.5,86.356 105.345,86.356 105.764,86.775 105.764,90.8 93.95,90.8 92.725,89.575
RTN on Bottom Layer "BOTTOM_LAYER_RTN_P173" (solid, remove dead copper, pour order 173): 131.7,74 133.7,74 134.655,74.955 139.159,74.955 139.614,75.41 139.614,78.799 137.963,80.45 133.325,80.45 132.35,79.475 132.35,77.175 131.7,77.175
RTN on Bottom Layer "BOTTOM_LAYER_RTN_P187" (solid, remove dead copper, pour order 187): 20 vertices, not listed, extent 112.025,81.125 118.15,85.825
RTN on Bottom Layer "BOTTOM_LAYER_RTN_P178" (solid, remove dead copper, pour order 178): 22 vertices, not listed, extent 103.175,83.4 128.1,90.8
PGND on Bottom Layer "BOTTOM_LAYER_PGND_P183" (solid, remove dead copper, pour order 183): 135.6,21.025 135.6,24.4 132.7,27.3 118.773,27.3 118.375,26.902 118.375,22.045 119.395,21.025
PGND on Bottom Layer "BOTTOM_LAYER_PGND_P182" (solid, remove dead copper, pour order 182): 35 vertices, not listed, extent 101.875,43.1 111.125,62.4
PGND on Bottom Layer "BOTTOM_LAYER_PGND_P181" (solid, remove dead copper, pour order 181): 122,53.175 126.1,53.175 126.9,52.375 126.9,50.4 124.75,50.4 124.6,50.55 124.175,50.55 123.825,50.2 123.575,50.2 123.2,50.575 122.55,50.575 122.55,52.25 122.575,52.275 122,52.85
SW on Bottom Layer "BOTTOM_LAYER_SW_P180" (solid, remove dead copper, pour order 180): 120.675,34.05 120.675,36.1 119.9,36.1 119.775,36.225 119.775,37.875 119.525,38.125 117.95,38.125 116.975,39.1 114.6,39.1 113.9,38.4 113.9,34.15 114.45,33.6 120.375,33.6 120.675,33.9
